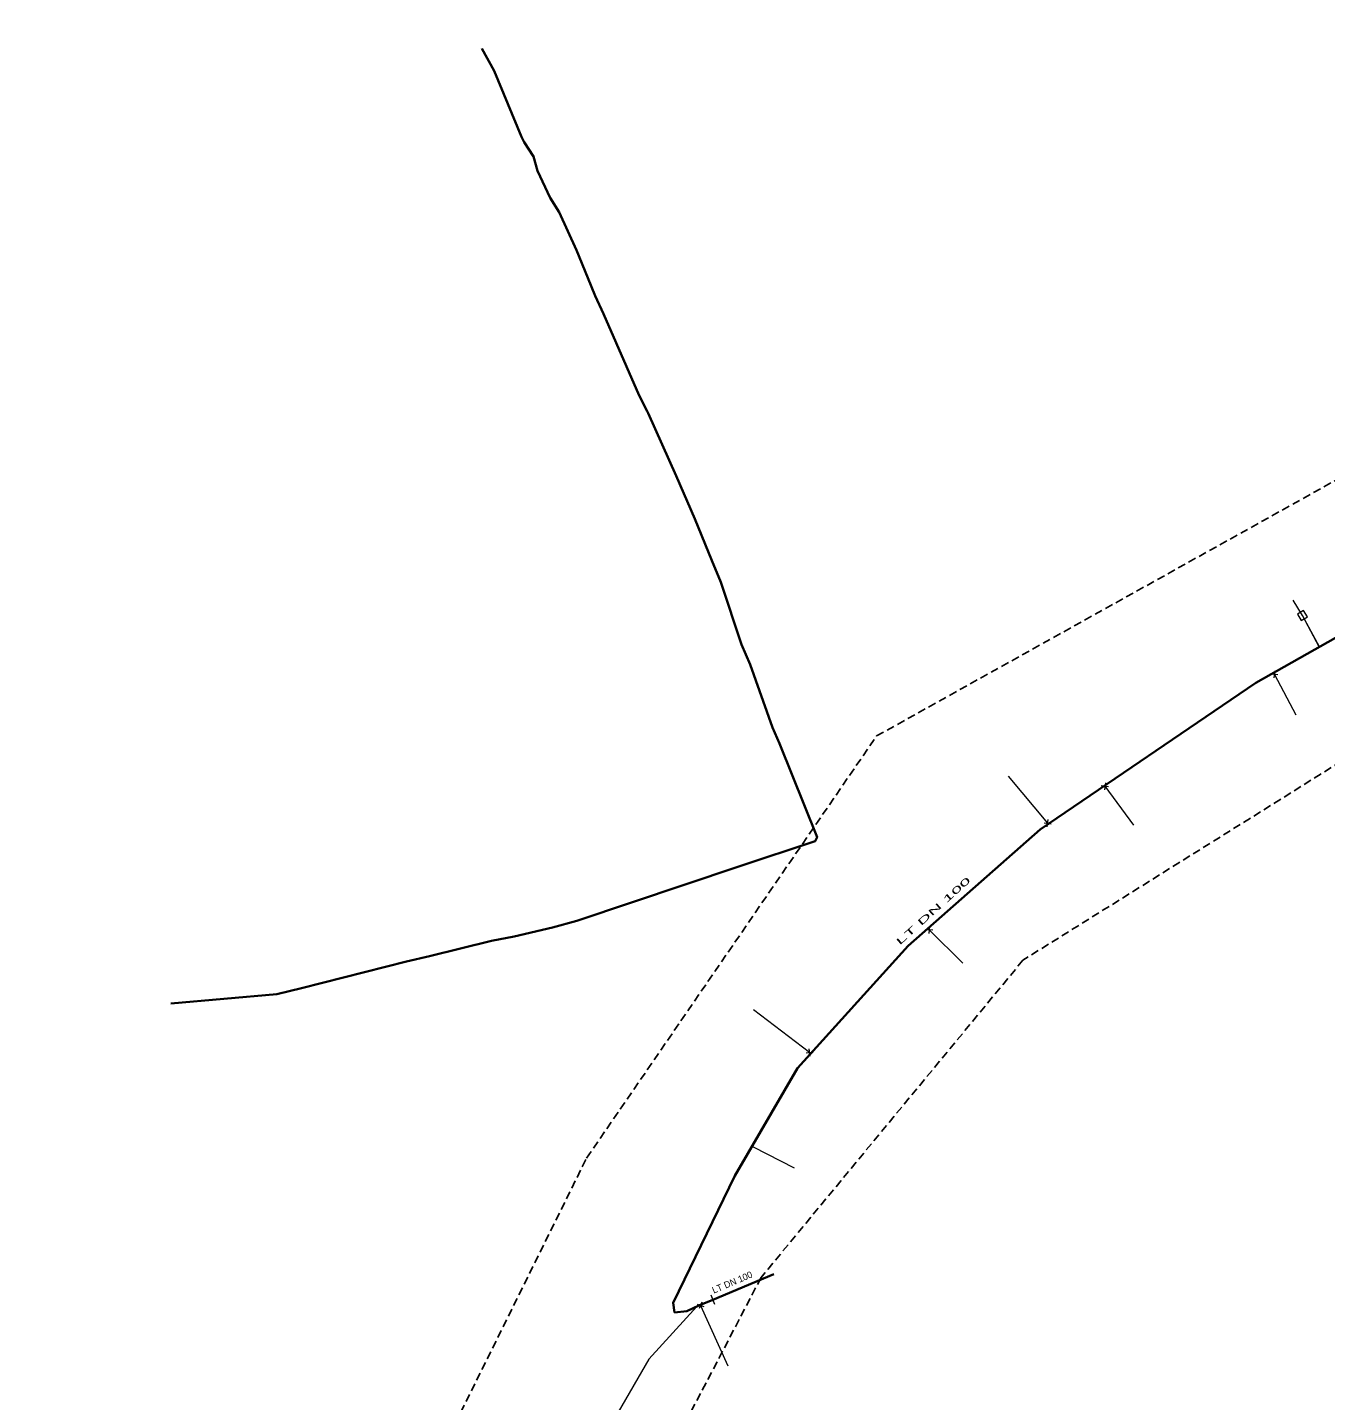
# Model space of a CAD drawing. Extents: x -743677 to -742923, y -1027084 to -1026416.
# Drawn here: x -743535.9 to -743300.4, y -1026831.6 to -1026582.5 of the extents above; entities that cross this region are included whole.
import ezdxf

# ---------------------------------------------------------------- set-up
doc = ezdxf.new("R2010")
doc.units = 0
doc.header["$LTSCALE"] = 0.48
doc.linetypes.add('MEDIUM_DASHED', pattern=[4.5, 3, -1.5])
for name, color, linetype, lineweight in [('15', 7, 'Continuous', 13), ('16', 7, 'Continuous', 35), ('21', 7, 'Continuous', 13), ('59', 7, 'Continuous', 13), ('62', 7, 'MEDIUM_DASHED', 25)]:
    doc.layers.add(name, color=color, linetype=linetype, lineweight=lineweight)
doc.layers.add('17', color=7, linetype='Continuous')

msp = doc.modelspace()

# ---------------------------------------------------------------- linework, layer by layer
at = {"layer": '15'}
for p, q in [((-743309.012, -1026699.929), (-743310.29, -1026699.748)), ((-743309.56, -1026699.196), (-743309.739, -1026700.486)), ((-743339.762, -1026720.212), (-743341.039, -1026720.026)), ((-743340.307, -1026719.477), (-743340.492, -1026720.765)), ((-743350.841, -1026727.473), (-743350.658, -1026726.184)), ((-743351.387, -1026726.738), (-743350.11, -1026726.923)), ((-743371.627, -1026746.215), (-743372.915, -1026746.143)), ((-743372.235, -1026745.531), (-743372.304, -1026746.831)), ((-743394.598, -1026768.512), (-743393.318, -1026768.349)), ((-743393.876, -1026769.074), (-743394.043, -1026767.783)), ((-743413.52, -1026813.688), (-743413.981, -1026814.893)), ((-743411.15, -1026814.162), (-743411.849, -1026812.436)), ((-743414.357, -1026814.059), (-743413.14, -1026814.521))]:
    msp.add_line(p, q, dxfattribs=at)
at = {"layer": '16'}
msp.add_line((-743400.474, -1026808.635), (-743411.5, -1026813.3), dxfattribs=at)
msp.add_line((-743400.474, -1026808.635), (-743411.5, -1026813.3), dxfattribs=at)
for points in [[(-743509.859, -1026759.519), (-743490.649, -1026757.829), (-743486.149, -1026756.75), (-743467.118, -1026751.94), (-743462.909, -1026750.94), (-743451.659, -1026748.16), (-743447.55, -1026747.362), (-743440.609, -1026745.739), (-743436.199, -1026744.559), (-743406.817, -1026734.69), (-743392.949, -1026730.1), (-743392.6, -1026729.359), (-743399.44, -1026712.35), (-743400.71, -1026709.48), (-743404.76, -1026698.01), (-743406.329, -1026694.39), (-743410.072, -1026683.104), (-743411.73, -1026679.17), (-743414.799, -1026671.605), (-743418.145, -1026663.831), (-743423.269, -1026652.469), (-743423.447, -1026652.111), (-743424.859, -1026649.269), (-743431.35, -1026634.429), (-743432.879, -1026631.17), (-743434.219, -1026627.899), (-743436.25, -1026622.879), (-743439.402, -1026615.993), (-743441.03, -1026613.41), (-743443.35, -1026608.489), (-743444.029, -1026605.871), (-743445.73, -1026603.309), (-743446.26, -1026602.3), (-743451.179, -1026590.32), (-743453.41, -1026586.269)], [(-743411.5, -1026813.3), (-743414.085, -1026814.3), (-743416.25, -1026815.359), (-743418.449, -1026815.57), (-743418.739, -1026813.859), (-743407.532, -1026790.787), (-743396.142, -1026771.28), (-743376.103, -1026749.078), (-743352.162, -1026727.984), (-743312.98, -1026701.342), (-743298.535, -1026693.171)], [(-743411.5, -1026813.3), (-743414.085, -1026814.3), (-743416.25, -1026815.359), (-743418.449, -1026815.57), (-743418.739, -1026813.859), (-743407.532, -1026790.787), (-743396.142, -1026771.28), (-743376.103, -1026749.078), (-743352.162, -1026727.984), (-743312.98, -1026701.342), (-743298.535, -1026693.171)]]:
    msp.add_lwpolyline(points, dxfattribs=at)
at = {"layer": '21'}
msp.add_lwpolyline([(-743303.659, -1026689.384), (-743304.334, -1026688.259), (-743305.459, -1026688.934), (-743304.784, -1026690.059)], close=True, dxfattribs=at)
at = {"layer": '59'}
for points in [[(-743301.477, -1026694.835), (-743304.56, -1026689.16), (-743306.219, -1026686.394)], [(-743301.491, -1026694.807), (-743304.56, -1026689.16), (-743306.219, -1026686.394)], [(-743309.852, -1026699.572), (-743309.65, -1026699.84), (-743305.775, -1026707.192)], [(-743309.852, -1026699.572), (-743309.65, -1026699.84), (-743305.775, -1026707.192)], [(-743350.653, -1026726.958), (-743350.75, -1026726.83), (-743357.876, -1026718.293)], [(-743350.653, -1026726.958), (-743350.75, -1026726.83), (-743357.876, -1026718.293)], [(-743340.466, -1026720.031), (-743340.4, -1026720.12), (-743335.201, -1026727.174)], [(-743340.466, -1026720.031), (-743340.4, -1026720.12), (-743335.201, -1026727.174)], [(-743372.51, -1026745.912), (-743372.27, -1026746.18), (-743366.156, -1026752.232)], [(-743372.51, -1026745.912), (-743372.27, -1026746.18), (-743366.156, -1026752.232)], [(-743393.729, -1026768.607), (-743393.96, -1026768.43), (-743404.124, -1026760.69)], [(-743393.729, -1026768.607), (-743393.96, -1026768.43), (-743404.124, -1026760.69)], [(-743404.422, -1026785.46), (-743404.23, -1026785.56), (-743396.742, -1026789.343)], [(-743414.432, -1026814.469), (-743414.413, -1026814.504), (-743423.161, -1026824.075), (-743428.699, -1026833.696), (-743447.419, -1026870.437), (-743441.249, -1026873.874)], [(-743413.785, -1026814.184), (-743413.75, -1026814.29), (-743408.818, -1026825.238)]]:
    msp.add_lwpolyline(points, dxfattribs=at)
at = {"layer": '62'}
msp.add_lwpolyline([(-743185.331, -1026452.124), (-743185.314, -1026452.115), (-743122.624, -1026517.483), (-743128.636, -1026561.04), (-743080.591, -1026678.626), (-742988.56, -1026728.316), (-742957.099, -1026715.401), (-742922.946, -1026754.658), (-742988.389, -1026762.896), (-743109.886, -1026711.598), (-743142.114, -1026640.576), (-743238.891, -1026678.985), (-743355.253, -1026751.681), (-743402.763, -1026809.228), (-743453.197, -1026905.826), (-743482.789, -1027084.226), (-743535.862, -1027074.436), (-743492.719, -1026905.289), (-743434.421, -1026787.581), (-743381.806, -1026711.007), (-743250.543, -1026637.895), (-743166.228, -1026600.23)], close=True, dxfattribs=at)

# ---------------------------------------------------------------- texts
at = {"layer": '17', "width": 2.25}
msp.add_text('LT DN 100 ', height=1.2, rotation=42, dxfattribs=at).set_placement((-743377.62, -1026749.022))
at = {"layer": '17'}
msp.add_text('LT DN 100 ', height=1.2, rotation=23, dxfattribs=at).set_placement((-743411.341, -1026812.176))

doc.saveas('drawing.dxf')
